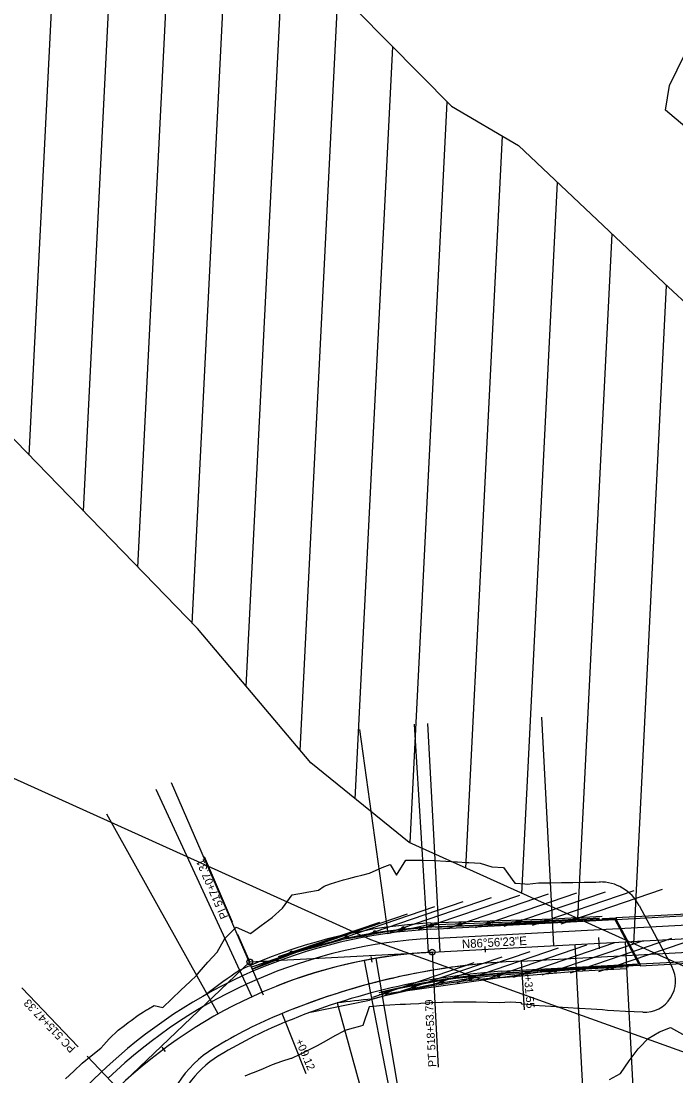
# Model space of a CAD drawing. Extents: x 1300404 to 1323571, y 237813 to 252077.
# Drawn here: x 1310113 to 1310687, y 241720 to 242643 of the extents above; entities that cross this region are included whole.
import ezdxf

# ---------------------------------------------------------------- set-up
doc = ezdxf.new("R2010")
doc.units = 0
for name, color, linetype in [('R_Bridge', 7, 'Continuous'), ('R_Const Limits', 7, 'Continuous'), ('R_Draft', 7, 'Continuous'), ('R_Floodway', 7, 'Continuous'), ('R_Flooplain', 7, 'Continuous'), ('R_Guardrail', 7, 'Continuous'), ('R_Horz Alg Annot', 7, 'Continuous'), ('R_Horz Alg Annot Leader', 7, 'Continuous'), ('R_Horz Alg Major Ticks', 7, 'Continuous'), ('R_Horz Alg Minor Ticks', 7, 'Continuous'), ('R_Horz Alg Tangents', 7, 'Continuous'), ('R_Horz Alg Tangents Text', 7, 'Continuous'), ('R_Lane Edge', 7, 'Continuous'), ('R_No Plot', 7, 'Continuous'), ('R_Proposed', 7, 'Continuous'), ('R_Shoulder', 7, 'Continuous'), ('T_Drafting', 7, 'Continuous')]:
    doc.layers.add(name, color=color, linetype=linetype)

msp = doc.modelspace()

# ---------------------------------------------------------------- linework, layer by layer
at = {"layer": 'R_Bridge'}
for p, q in [((1310634.41, 241858.98), (1310813.05, 241868.54)), ((1310634.49, 241857.41), (1310813.13, 241866.96)), ((1310622.43, 241858.18), (1310634.42, 241858.82)), ((1310622.49, 241857.18), (1310622.43, 241858.18)), ((1310626.98, 241857.42), (1310622.49, 241857.18)), ((1310634.49, 241857.4), (1310626.98, 241857.42)), ((1310633.36, 241857.41), (1310654.18, 241818.34)), ((1310634.49, 241857.4), (1310634.41, 241859)), ((1310634.42, 241858.82), (1310634.49, 241857.4)), ((1310634.49, 241857.4), (1310655.25, 241818.46)), ((1310655.25, 241818.46), (1310833.89, 241828.01)), ((1310655.34, 241816.88), (1310833.98, 241826.43)), ((1310643.29, 241817.4), (1310647.79, 241817.64)), ((1310643.35, 241816.4), (1310643.29, 241817.4)), ((1310655.33, 241817.06), (1310643.35, 241816.4)), ((1310647.79, 241817.64), (1310655.25, 241818.46)), ((1310655.34, 241816.89), (1310655.25, 241818.46)), ((1310655.25, 241818.46), (1310655.33, 241817.06))]:
    msp.add_line(p, q, dxfattribs=at)
at = {"layer": 'R_Const Limits'}
for points in [[(1310152.44, 241717.78), (1310159.67, 241724.68), (1310166.96, 241731.53), (1310174.88, 241738.04), (1310183.35, 241744.83), (1310185.83, 241747.69), (1310190.62, 241752.98), (1310198.51, 241760.47), (1310204, 241764.69), (1310207.15, 241767.07), (1310209.75, 241769), (1310215.91, 241773.49), (1310220.48, 241776.44), (1310223.27, 241778.13), (1310224.2, 241778.69), (1310225.13, 241779.25), (1310229.82, 241782.01), (1310237.51, 241780.3), (1310245.39, 241787.82), (1310253.29, 241795.5), (1310261.33, 241803.16), (1310267.09, 241808.42), (1310269.34, 241811.12), (1310277.05, 241819.98), (1310285.03, 241828.73), (1310291.75, 241840.7), (1310301.62, 241850.57), (1310314.43, 241844.91), (1310323.7, 241852.01), (1310333.19, 241858.91), (1310342.43, 241867.1), (1310350.87, 241878.74), (1310362.35, 241880.88), (1310363.64, 241881.13), (1310373.79, 241883.01), (1310378.91, 241886.52), (1310384.43, 241888.47), (1310395.62, 241891.94), (1310400.29, 241893.23), (1310406.94, 241894.99), (1310411.64, 241896.17), (1310418.36, 241897.7), (1310429.6, 241902.77), (1310436.45, 241905.33), (1310442.11, 241896.06), (1310450.32, 241909.24), (1310452.63, 241909.27), (1310464.55, 241909.23), (1310475.29, 241908.91), (1310475.77, 241908.89), (1310485.34, 241908.3), (1310494.51, 241907.77), (1310495.38, 241907.72), (1310503.48, 241907.26), (1310505.43, 241907.13), (1310515.48, 241906.49), (1310525.66, 241903.34), (1310535.7, 241902.81), (1310545.58, 241888.96), (1310546.46, 241888.93), (1310554.55, 241888.58), (1310556.51, 241888.13), (1310566.46, 241889.45), (1310576.48, 241889.39), (1310576.96, 241889.38), (1310586.48, 241889.51), (1310595.62, 241889.65), (1310596.49, 241889.67), (1310606.49, 241889.85), (1310616.5, 241890.04), (1310620.73, 241890.13), (1310620.77, 241890.11)], [(1310654.61, 241869.62), (1310683.17, 241816.04)], [(1310657.78, 241776.13), (1310657.78, 241776.13), (1310642.57, 241776.93), (1310632.53, 241777.45), (1310626.73, 241777.8), (1310622.48, 241778.16), (1310612.43, 241778.78), (1310602.38, 241779.49), (1310601.5, 241779.55), (1310592.33, 241780.14), (1310582.76, 241780.74), (1310582.28, 241780.77), (1310572.24, 241781.37), (1310562.18, 241782.17), (1310560.22, 241782.52), (1310552.11, 241783.28), (1310551.18, 241784.27), (1310542, 241784.95), (1310532.01, 241784.51), (1310521.98, 241784.76), (1310511.96, 241784.98), (1310510.01, 241785.01), (1310501.94, 241785.09), (1310501.07, 241785.09), (1310491.93, 241785.02), (1310482.4, 241784.82), (1310481.92, 241784.79), (1310472.33, 241784.29), (1310463.37, 241783.72), (1310461.63, 241783.58), (1310454.39, 241783.25), (1310449.89, 241783.03), (1310445.39, 241782.79), (1310436.37, 241782.22), (1310431.05, 241781.93), (1310427.29, 241781.73), (1310421.99, 241781.22), (1310418.25, 241780.85), (1310412.69, 241764.49), (1310408.48, 241763.36), (1310404.28, 241762.18), (1310396.85, 241760.04), (1310395.96, 241759.58), (1310388.13, 241755.41), (1310380.4, 241751.19), (1310372.78, 241746.9), (1310365.14, 241742.84), (1310357.43, 241739.07), (1310350.09, 241735.75), (1310349.63, 241735.61), (1310341.46, 241732.94), (1310333.35, 241730.05), (1310325.51, 241726.54), (1310317.4, 241723.47), (1310314.9, 241722.64), (1310309.35, 241720.2)], [(1310628.59, 241717.21), (1310638.32, 241722.5), (1310645.83, 241733.71), (1310653.82, 241744.11), (1310654.75, 241745.22), (1310662.42, 241753.21), (1310672.3, 241758.99), (1310682.14, 241762.89), (1310695.17, 241755.66), (1310706.32, 241753.92), (1310707.57, 241753.78), (1310717.84, 241751.11), (1310728.47, 241750.91), (1310733.3, 241751.02), (1310737.75, 241750.82), (1310739.04, 241750.92), (1310745.98, 241755.04)]]:
    msp.add_lwpolyline(points, dxfattribs=at)
for centre, radius, start, end in [((1310620.47, 241851.42), 38.69, 28.06037, 91.0815), ((1310659.2, 241803.26), 27.17, 267.01792, 28.06037)]:
    msp.add_arc(centre, radius, start, end, dxfattribs=at)
at = {"layer": 'R_Draft'}
for centre, radius, start, end in [((1310574.96, 241212.44), 608.93, 93.92671, 112.49959), ((1310496.44, 241396.96), 408.42, 112.22818, 121.63465), ((1310334.67, 241659.55), 100, 121.63465, 223.66667)]:
    msp.add_arc(centre, radius, start, end, dxfattribs=at)
at = {"layer": 'R_Floodway'}
for p, q in [((1310120.52, 242263.51), (1310158.59, 243023.4)), ((1310168.12, 242214.45), (1310204.93, 242949.24)), ((1310215.73, 242165.39), (1310251.56, 242880.55)), ((1310263.33, 242116.34), (1310298.03, 242808.92)), ((1310310.63, 242061.1), (1310344.44, 242736.08)), ((1310357.89, 242005.22), (1310391.15, 242669.07)), ((1310405.84, 241962.93), (1310438.79, 242620.79)), ((1310453.96, 241924.23), (1310486.44, 242572.51)), ((1310502.92, 241902.19), (1310535, 242542.48)), ((1310551.88, 241880.16), (1310583.03, 242502.09)), ((1310600.84, 241858.12), (1310630.83, 242456.91)), ((1310649.79, 241836.08), (1310678.64, 242411.79))]:
    msp.add_line(p, q, dxfattribs=at)
for points in [[(1313830.5, 242013.29), (1313725.05, 241936.34), (1313624.18, 241854.31), (1313605.13, 241763.33), (1313491.24, 241614.21), (1313390.85, 241541.84), (1313238.35, 241394.67), (1313129.75, 241351.75), (1313002.33, 241319.46), (1312893.25, 241266.88), (1312749.18, 241191.87), (1312719.26, 241174.03), (1312375.34, 241167.16), (1311696.89, 241341.68), (1311497.53, 241419.47), (1311333.82, 241508.77), (1311059.08, 241652.06), (1310740.78, 241795.13), (1310453.25, 241924.55), (1310367.2, 241994.21), (1310267.81, 242111.73), (1309996.24, 242391.57), (1309869.69, 242546.75), (1309624.53, 242919.62)], [(1310379.63, 242680.75), (1310490.18, 242568.72), (1310548.96, 242534.3), (1310676.05, 242414.18), (1310731.56, 242362.99), (1310810.26, 242291.28), (1310887.62, 242241.41), (1310974.87, 242195.88), (1311031.59, 242168.82), (1311109.67, 242133.43), (1311173.76, 242108.43), (1311242.66, 242083.18), (1311339.33, 242032.34), (1311351.04, 242024.49), (1311431.54, 241940.59), (1311405.15, 241750.77), (1311416.02, 241677.63), (1311441.14, 241598.94), (1311547.83, 241506.46), (1311691.44, 241475.03), (1311836.73, 241477.39), (1311974.41, 241472.87)]]:
    msp.add_lwpolyline(points, dxfattribs=at)
at = {"layer": 'R_Flooplain'}
for p, q in [((1310681.02, 242586.93), (1310721.43, 242669.58)), ((1310677.53, 242565.33), (1310681.02, 242586.93)), ((1310735.58, 242516.43), (1310677.53, 242565.33))]:
    msp.add_line(p, q, dxfattribs=at)
msp.add_lwpolyline([(1309009.78, 242685.04), (1309044.07, 242596.21), (1309055.9, 242542.38), (1309352.07, 242367.77), (1309503.16, 242292.41), (1309669.46, 242230.8), (1309815.49, 242150.85), (1309936.66, 242057.64), (1310419.39, 241839.75), (1310733.16, 241727.16), (1311043.67, 241597.79), (1311103.17, 241577.86), (1311152.77, 241553.58), (1311178, 241525.7), (1311328.48, 241486.66), (1311553.07, 241380.98), (1311870.34, 241289.99), (1312137.52, 241213.62)], dxfattribs=at)
at = {"layer": 'R_Guardrail'}
for p, q in [((1310511.24, 241850.43), (1310599.99, 241880.64)), ((1310536.27, 241851.39), (1310625.02, 241881.6)), ((1310561.3, 241852.34), (1310650.05, 241882.55)), ((1310586.22, 241853.58), (1310674.97, 241883.79)), ((1310411.75, 241842.68), (1310500.49, 241872.89)), ((1310436.53, 241846.2), (1310525.27, 241876.41)), ((1310461.44, 241848.48), (1310550.19, 241878.69)), ((1310486.44, 241849.55), (1310575.18, 241879.76)), ((1310362.89, 241831.94), (1310451.63, 241862.15)), ((1310387.04, 241838.35), (1310475.79, 241868.56)), ((1310338.78, 241824.88), (1310427.53, 241855.09)), ((1310476.24, 241850.95), (1310576.21, 241854.29)), ((1310476.27, 241850.53), (1310619.81, 241858.2)), ((1310478.79, 241851.08), (1310578.8, 241854.84)), ((1310498.67, 241852.07), (1310496.71, 241853.04)), ((1310523.48, 241852.95), (1310521.51, 241853.92)), ((1310548.51, 241853.91), (1310546.54, 241854.87)), ((1310573.54, 241854.86), (1310571.57, 241855.83)), ((1310619.9, 241856.62), (1310576.21, 241854.29)), ((1310578.8, 241854.84), (1310622.49, 241857.18)), ((1310598.46, 241856.1), (1310596.49, 241857.07)), ((1310315.54, 241815.87), (1310404.29, 241846.08)), ((1310423.99, 241845.2), (1310422.02, 241846.17)), ((1310448.76, 241848.72), (1310446.8, 241849.69)), ((1310473.68, 241851), (1310471.71, 241851.97)), ((1310472.18, 241850.73), (1310478.86, 241851.09)), ((1310375.13, 241834.46), (1310373.16, 241835.43)), ((1310399.28, 241840.87), (1310397.31, 241841.84)), ((1310519.97, 241804.91), (1310608.72, 241835.12)), ((1310544.64, 241806.89), (1310633.39, 241837.1)), ((1310569.5, 241808.81), (1310658.24, 241839.02)), ((1310594.38, 241810.62), (1310683.13, 241840.83)), ((1310619.4, 241811.84), (1310708.15, 241842.05)), ((1310351.02, 241827.4), (1310349.05, 241828.37)), ((1310445.92, 241794.48), (1310534.67, 241824.69)), ((1310470.45, 241799.13), (1310559.19, 241829.34)), ((1310495.16, 241802.15), (1310583.91, 241832.36)), ((1310327.78, 241818.39), (1310325.81, 241819.36)), ((1310421.48, 241789.46), (1310510.22, 241819.67)), ((1310596.97, 241815.34), (1310427, 241791.26)), ((1310640.74, 241816.09), (1310533.83, 241810.38)), ((1310596.97, 241815.34), (1310640.66, 241817.68)), ((1310599.61, 241815.06), (1310643.29, 241817.4)), ((1310631.64, 241814.36), (1310629.67, 241815.33)), ((1310532.21, 241807.43), (1310530.24, 241808.4)), ((1310533.75, 241809.96), (1310599.61, 241815.06)), ((1310556.88, 241809.41), (1310554.92, 241810.38)), ((1310581.73, 241811.33), (1310579.77, 241812.3)), ((1310606.62, 241813.14), (1310604.65, 241814.11)), ((1310458.16, 241797), (1310456.2, 241797.96)), ((1310482.68, 241801.65), (1310480.72, 241802.62)), ((1310507.4, 241804.67), (1310505.44, 241805.64)), ((1310433.71, 241791.98), (1310431.75, 241792.94))]:
    msp.add_line(p, q, dxfattribs=at)
for points in [[(1310474.02, 241851.39), (1310471.8, 241852.48)], [(1310474.18, 241851.86), (1310472.08, 241852.89)], [(1310474.14, 241852.43), (1310472.56, 241853.21)], [(1310499.02, 241852.45), (1310496.8, 241853.54)], [(1310497.96, 241851.83), (1310496.95, 241852.33)], [(1310499.17, 241852.93), (1310497.08, 241853.96)], [(1310499.14, 241853.5), (1310497.55, 241854.28)], [(1310497.96, 241851.8), (1310510.45, 241852.27)], [(1310510.45, 241852.27), (1310522.94, 241852.74)], [(1310523.82, 241853.34), (1310521.6, 241854.43)], [(1310522.77, 241852.71), (1310521.75, 241853.21)], [(1310523.98, 241853.81), (1310521.89, 241854.84)], [(1310523.94, 241854.38), (1310522.36, 241855.16)], [(1310522.94, 241852.74), (1310547.92, 241853.68)], [(1310548.85, 241854.29), (1310546.63, 241855.38)], [(1310547.8, 241853.66), (1310546.78, 241854.16)], [(1310549.01, 241854.76), (1310546.92, 241855.79)], [(1310548.97, 241855.33), (1310547.39, 241856.11)], [(1310547.92, 241853.68), (1310560.41, 241854.15)], [(1310560.41, 241854.15), (1310572.9, 241854.62)], [(1310573.89, 241855.24), (1310571.66, 241856.33)], [(1310572.83, 241854.62), (1310571.82, 241855.12)], [(1310574.04, 241855.72), (1310571.95, 241856.75)], [(1310574.01, 241856.28), (1310572.42, 241857.07)], [(1310572.9, 241854.62), (1310578.8, 241854.84), (1310597.87, 241855.86)], [(1310598.81, 241856.48), (1310596.58, 241857.57)], [(1310597.75, 241855.86), (1310596.73, 241856.36)], [(1310598.96, 241856.95), (1310596.87, 241857.98)], [(1310598.92, 241857.52), (1310597.34, 241858.3)], [(1310597.87, 241855.86), (1310610.36, 241856.53)], [(1310610.36, 241856.53), (1310622.49, 241857.18)], [(1310399.75, 241842.3), (1310398.16, 241843.08)], [(1310411.18, 241842.85), (1310423.49, 241845.02)], [(1310424.33, 241845.59), (1310422.11, 241846.68)], [(1310423.28, 241844.96), (1310422.26, 241845.46)], [(1310424.49, 241846.06), (1310422.39, 241847.09)], [(1310424.45, 241846.63), (1310422.86, 241847.41)], [(1310423.49, 241845.02), (1310438.63, 241847.68), (1310448.22, 241848.55)], [(1310449.11, 241849.1), (1310446.89, 241850.19)], [(1310448.05, 241848.48), (1310447.04, 241848.98)], [(1310449.26, 241849.58), (1310447.17, 241850.61)], [(1310449.23, 241850.14), (1310447.64, 241850.93)], [(1310448.22, 241848.55), (1310460.67, 241849.68)], [(1310460.67, 241849.68), (1310472.18, 241850.73), (1310473.12, 241850.78)], [(1310472.97, 241850.76), (1310471.95, 241851.26)], [(1310473.12, 241850.78), (1310478.86, 241851.09), (1310478.79, 241851.08), (1310497.96, 241851.8)], [(1310362.67, 241830.94), (1310374.72, 241834.26)], [(1310375.47, 241834.84), (1310373.25, 241835.94)], [(1310374.42, 241834.22), (1310373.4, 241834.72)], [(1310375.63, 241835.32), (1310373.53, 241836.35)], [(1310375.59, 241835.89), (1310374, 241836.67)], [(1310374.72, 241834.26), (1310396.65, 241840.28), (1310398.87, 241840.68)], [(1310399.63, 241841.25), (1310397.41, 241842.35)], [(1310398.57, 241840.63), (1310397.56, 241841.13)], [(1310399.78, 241841.73), (1310397.69, 241842.76)], [(1310398.87, 241840.68), (1310411.18, 241842.85)], [(1310327.38, 241818.31), (1310350.76, 241827.17)], [(1310351.36, 241827.78), (1310349.14, 241828.87)], [(1310350.31, 241827.16), (1310349.29, 241827.66)], [(1310351.52, 241828.26), (1310349.43, 241829.29)], [(1310351.48, 241828.83), (1310349.9, 241829.61)], [(1310350.76, 241827.17), (1310355.55, 241828.99), (1310362.67, 241830.94)], [(1310315.7, 241813.89), (1310327.38, 241818.31)], [(1310328.13, 241818.77), (1310325.91, 241819.87)], [(1310327.07, 241818.15), (1310326.06, 241818.65)], [(1310328.28, 241819.25), (1310326.19, 241820.28)], [(1310328.25, 241819.82), (1310326.66, 241820.6)], [(1310605.85, 241815.39), (1310599.61, 241815.06), (1310593.38, 241814.58)], [(1310607.08, 241814.56), (1310605.5, 241815.35)], [(1310630.81, 241816.73), (1310605.85, 241815.39)], [(1310631.99, 241814.74), (1310629.77, 241815.83)], [(1310632.14, 241815.22), (1310630.05, 241816.25)], [(1310632.11, 241815.79), (1310630.52, 241816.57)], [(1310643.29, 241817.4), (1310630.81, 241816.73)], [(1310506.49, 241806.95), (1310494.07, 241805.59)], [(1310507.75, 241805.05), (1310505.53, 241806.15)], [(1310507.9, 241805.53), (1310505.81, 241806.56)], [(1310507.87, 241806.1), (1310506.28, 241806.88)], [(1310531.34, 241809.69), (1310506.49, 241806.95)], [(1310532.56, 241807.81), (1310530.33, 241808.9)], [(1310531.5, 241807.19), (1310530.48, 241807.69)], [(1310532.71, 241808.29), (1310530.62, 241809.32)], [(1310532.67, 241808.86), (1310531.09, 241809.64)], [(1310543.52, 241810.71), (1310533.75, 241809.96), (1310533.88, 241809.96), (1310531.34, 241809.69)], [(1310555.99, 241811.68), (1310543.52, 241810.71)], [(1310557.23, 241809.79), (1310555.01, 241810.88)], [(1310556.17, 241809.17), (1310555.16, 241809.67)], [(1310557.38, 241810.27), (1310555.29, 241811.3)], [(1310557.35, 241810.83), (1310555.76, 241811.62)], [(1310580.91, 241813.61), (1310555.99, 241811.68)], [(1310582.08, 241811.71), (1310579.86, 241812.81)], [(1310581.02, 241811.09), (1310580.01, 241811.59)], [(1310582.23, 241812.19), (1310580.14, 241813.22)], [(1310582.2, 241812.76), (1310580.61, 241813.54)], [(1310593.38, 241814.58), (1310580.91, 241813.61)], [(1310606.96, 241813.52), (1310604.74, 241814.61)], [(1310605.91, 241812.9), (1310604.89, 241813.4)], [(1310607.12, 241814), (1310605.02, 241815.03)], [(1310630.93, 241814.12), (1310629.92, 241814.62)], [(1310444.87, 241796.8), (1310437.2, 241795.32), (1310432.65, 241794.21)], [(1310457.14, 241799.18), (1310444.87, 241796.8)], [(1310458.51, 241797.38), (1310456.29, 241798.47)], [(1310457.45, 241796.75), (1310456.44, 241797.25)], [(1310458.66, 241797.85), (1310456.57, 241798.88)], [(1310458.63, 241798.42), (1310457.04, 241799.2)], [(1310481.69, 241803.93), (1310457.14, 241799.18)], [(1310483.03, 241802.04), (1310480.81, 241803.13)], [(1310481.97, 241801.41), (1310480.96, 241801.91)], [(1310483.18, 241802.51), (1310481.09, 241803.54)], [(1310483.15, 241803.08), (1310481.56, 241803.86)], [(1310494.07, 241805.59), (1310485.24, 241804.62), (1310481.69, 241803.93)], [(1310506.69, 241804.43), (1310505.68, 241804.93)], [(1310432.65, 241794.21), (1310428.84, 241793.28)], [(1310434.06, 241792.36), (1310431.84, 241793.45)], [(1310433, 241791.73), (1310431.99, 241792.23)], [(1310434.21, 241792.83), (1310432.12, 241793.86)], [(1310434.18, 241793.4), (1310432.59, 241794.18)]]:
    msp.add_lwpolyline(points, dxfattribs=at)
for centre in [(1310472.96, 241852.03), (1310497.96, 241853.09), (1310522.76, 241853.98), (1310547.79, 241854.93), (1310572.82, 241855.88), (1310597.74, 241857.12), (1310398.56, 241841.9), (1310423.27, 241846.23), (1310448.05, 241849.74), (1310374.41, 241835.48), (1310350.3, 241828.42), (1310327.06, 241819.41), (1310605.9, 241814.16), (1310630.92, 241815.38), (1310506.68, 241805.69), (1310531.49, 241808.45), (1310556.16, 241810.43), (1310581.01, 241812.35), (1310457.44, 241798.02), (1310481.97, 241802.68), (1310433, 241793)]:
    msp.add_circle(centre, 1.25, dxfattribs=at)
for centre, radius, start, end in [((1310496.44, 241396.96), 454.42, 93.06037, 113.43723), ((1310574.96, 241212.44), 599.35, 93.93245, 104.32469), ((1310574.96, 241212.44), 598.93, 93.93245, 104.12033)]:
    msp.add_arc(centre, radius, start, end, dxfattribs=at)
at = {"layer": 'R_Horz Alg Annot Leader'}
for points in [[(1310298.64, 241854.84), (1310273.94, 241912.02)], [(1310313.6, 241820.22), (1310303.29, 241844.08)], [(1310473.35, 241828.76), (1310478.73, 241728.1)], [(1310554.29, 241778.18), (1310551.65, 241820.93)], [(1310163.47, 241745.8), (1310114.16, 241797.46)], [(1310363.17, 241722.32), (1310341.93, 241775.02)], [(1310197.87, 241709.76), (1310171.2, 241737.69)]]:
    msp.add_lwpolyline(points, dxfattribs=at)
at = {"layer": 'R_Horz Alg Major Ticks'}
msp.add_lwpolyline([(1310619.09, 241841.56), (1310619.62, 241831.57)], dxfattribs=at)
at = {"layer": 'R_Horz Alg Minor Ticks'}
for points in [[(1310519.37, 241833.72), (1310519.63, 241828.73)], [(1310419.52, 241825.02), (1310420.4, 241820.1)], [(1310323.45, 241795.99), (1310325.44, 241791.41)], [(1310236.6, 241745.72), (1310239.58, 241741.71)]]:
    msp.add_lwpolyline(points, dxfattribs=at)
at = {"layer": 'R_Horz Alg Tangents'}
for p, q in [((1310313.6, 241820.22), (1310473.35, 241828.76)), ((1310197.87, 241709.76), (1310313.6, 241820.22))]:
    msp.add_line(p, q, dxfattribs=at)
at = {"layer": 'R_Lane Edge'}
for p, q in [((1310472.71, 241840.74), (1310917.76, 241864.54)), ((1310551.65, 241820.93), (1310919.04, 241840.57))]:
    msp.add_line(p, q, dxfattribs=at)
for centre, radius, start, end in [((1310496.44, 241396.96), 444.42, 93.06037, 133.66667), ((1310574.96, 241212.44), 608.93, 92.19403, 112.49959), ((1310496.44, 241396.96), 408.42, 112.22818, 121.63465), ((1310334.67, 241659.55), 100, 121.63465, 223.66667)]:
    msp.add_arc(centre, radius, start, end, dxfattribs=at)
at = {"layer": 'R_No Plot'}
for p, q in [((1310470.05, 241828.57), (1310457.85, 242028.2)), ((1310469.36, 242028.83), (1310480.04, 241829.12)), ((1310579.89, 241834.46), (1310569.22, 242034.17)), ((1310409.83, 242023.42), (1310434.48, 241845.11)), ((1310244.9, 241977.2), (1310324.45, 241793.7)), ((1310231.55, 241971.23), (1310315.32, 241789.62)), ((1310285.91, 241774.67), (1310188.54, 241949.36)), ((1310434.48, 241845.11), (1310468.58, 241852.69)), ((1310468.58, 241852.69), (1310576.12, 241856.29)), ((1310576.12, 241856.29), (1310619.79, 241858.62)), ((1310609.19, 241635.74), (1310598.52, 241835.45)), ((1310642.2, 241837.79), (1310652.88, 241638.07)), ((1310452.23, 241625.13), (1310414.19, 241821.48)), ((1310424.03, 241823.27), (1310457.52, 241626.09)), ((1310645.37, 241815.93), (1310597.09, 241813.34)), ((1310597.09, 241813.34), (1310533.97, 241808.7)), ((1310366.77, 241776.16), (1310418.47, 241786.73)), ((1310390.21, 241784.27), (1310434.96, 241621.1))]:
    msp.add_line(p, q, dxfattribs=at)
msp.add_arc((1310585.63, 241222.6), 588.38, 95.03659, 106.50544, dxfattribs=at)
at = {"layer": 'R_Proposed'}
msp.add_line((1310473.35, 241828.76), (1310918.4, 241852.55), dxfattribs=at)
for centre in [(1310473.35, 241828.76), (1310313.6, 241820.22)]:
    msp.add_circle(centre, 2.5, dxfattribs=at)
for start, end in [(93.06037, 133.66667), (93.06037, 111.63325), (94.98457, 111.63325), (94.98457, 111.63325)]:
    msp.add_arc((1310496.44, 241396.96), 432.42, start, end, dxfattribs=at)
at = {"layer": 'R_Shoulder'}
for p, q in [((1310471.99, 241854.22), (1310478.67, 241854.58)), ((1310472.28, 241848.73), (1310633.36, 241857.34)), ((1310478.67, 241854.58), (1310578.64, 241857.92)), ((1310578.64, 241857.92), (1310622.32, 241860.26)), ((1310533.75, 241811.96), (1310654.15, 241818.4)), ((1310534.04, 241806.47), (1310599.77, 241811.99)), ((1310599.77, 241811.99), (1310643.46, 241814.32)), ((1310137.98, 241680.24), (1310184.06, 241724.22))]:
    msp.add_line(p, q, dxfattribs=at)
for centre, radius, start, end in [((1310496.44, 241396.96), 457.92, 93.06037, 113.43723), ((1310496.44, 241396.96), 452.42, 93.06037, 133.66667), ((1310496.44, 241396.96), 457.92, 113.43723, 114.76223), ((1310560.7, 241429.62), 460.84, 123.75525, 128.12775), ((1310574.96, 241212.44), 600.93, 93.93245, 112.5014), ((1310574.96, 241212.44), 595.43, 93.93245, 104.12033), ((1310470.06, 241186.53), 603.05, 94.68948, 97.60926), ((1310574.96, 241212.44), 595.43, 104.12033, 105.00891), ((1310496.44, 241396.96), 400.42, 112.22547, 122.09161), ((1310334.67, 241659.55), 92, 121.63465, 212.98944)]:
    msp.add_arc(centre, radius, start, end, dxfattribs=at)
at = {"layer": 'T_Drafting'}
msp.add_line((1310473.35, 241828.76), (1310918.4, 241852.55), dxfattribs=at)

# ---------------------------------------------------------------- texts
at = {"layer": 'R_Horz Alg Annot'}
for s, rotation, p in [('PI 517+07.31', 113.36352, (1310294.96, 241859.58)), ('+31.55', 274.79595, (1310553.69, 241808.06)), ('PC 515+47.33', 133.66667, (1310161.65, 241744.86)), ('PT 518+53.79', 93.06037, (1310477.04, 241728.47)), ('+09.12', 293.20459, (1310353.37, 241751.14))]:
    msp.add_text(s, height=7, rotation=rotation, dxfattribs=at).set_placement(p)
at = {"layer": 'R_Horz Alg Tangents Text'}
msp.add_text('N86%%d56\'23"E', height=7.5, rotation=3.06037, dxfattribs=at).set_placement((1310499.59, 241832.05))

doc.saveas('drawing.dxf')
